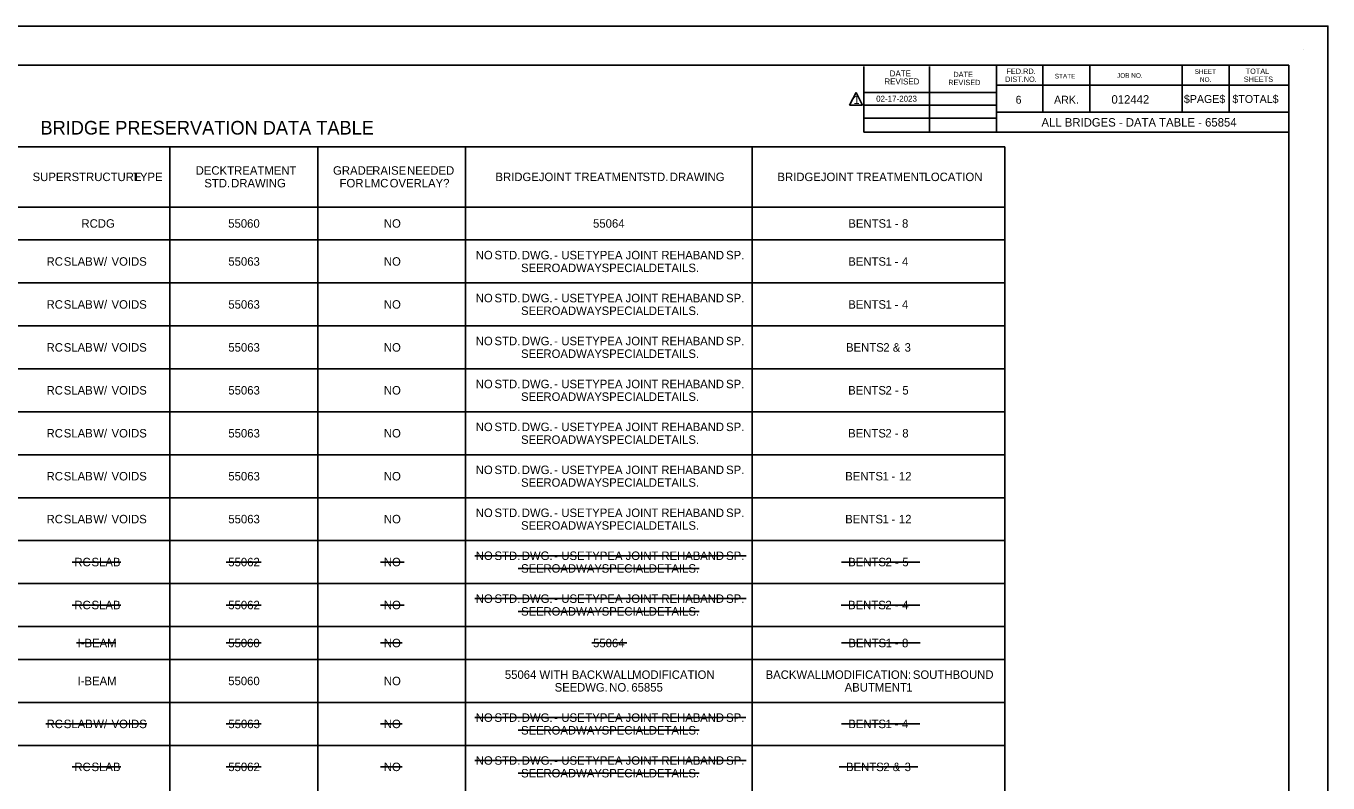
# Model space of a CAD drawing. Extents: x 18 to 14744716, y -5 to 1829144.
# Drawn here: x 32.59 to 51.78, y 5.47 to 16.63 of the extents above; entities that cross this region are included whole.
import ezdxf

# ---------------------------------------------------------------- set-up
doc = ezdxf.new("R2010")
doc.units = 0
for name, color, linetype in [('B_Copy In', 7, 'Continuous'), ('B_Dimensions', 7, 'Continuous'), ('B_Text', 7, 'Continuous'), ('B_Title Text', 7, 'Continuous'), ('R_Border', 7, 'Continuous'), ('R_No Plot', 7, 'Continuous')]:
    doc.layers.add(name, color=color, linetype=linetype)

msp = doc.modelspace()

# ---------------------------------------------------------------- linework, layer by layer
at = {"layer": 'B_Dimensions'}
for p, q in [((44.822, 15.648), (44.726, 15.464)), ((44.919, 15.464), (44.822, 15.648)), ((44.726, 15.464), (44.919, 15.464)), ((33.27, 8.729), (33.984, 8.729)), ((35.539, 8.729), (36.056, 8.729)), ((37.812, 8.729), (38.163, 8.729)), ((39.206, 8.823), (43.201, 8.823)), ((42.509, 8.636), (39.842, 8.636)), ((44.606, 8.729), (45.764, 8.729)), ((33.27, 8.096), (33.984, 8.096)), ((35.539, 8.096), (36.056, 8.096)), ((37.812, 8.096), (38.163, 8.096)), ((39.206, 8.19), (43.201, 8.19)), ((44.603, 8.096), (45.761, 8.096)), ((42.509, 8.003), (39.842, 8.003)), ((33.333, 7.537), (33.915, 7.537)), ((35.54, 7.537), (36.057, 7.537)), ((37.812, 7.537), (38.133, 7.537)), ((40.928, 7.537), (41.445, 7.537)), ((44.607, 7.537), (45.765, 7.537)), ((32.881, 6.344), (34.368, 6.344)), ((35.54, 6.344), (36.057, 6.344)), ((37.812, 6.344), (38.133, 6.344)), ((39.206, 6.438), (43.2, 6.438)), ((44.606, 6.345), (45.764, 6.345)), ((42.508, 6.251), (39.841, 6.251)), ((39.206, 5.805), (43.201, 5.805)), ((33.269, 5.712), (33.984, 5.712)), ((35.538, 5.712), (36.055, 5.712)), ((37.812, 5.712), (38.133, 5.712)), ((42.509, 5.618), (39.842, 5.618)), ((44.573, 5.712), (45.731, 5.712))]:
    msp.add_line(p, q, dxfattribs=at)
at = {"layer": 'B_Text'}
for p, q in [((23.2, 14.85), (47.013, 14.85)), ((34.711, -1.614), (34.711, 14.85)), ((36.889, -1.614), (36.889, 14.85)), ((39.067, -1.614), (39.067, 14.85)), ((43.29, -1.614), (43.29, 14.85)), ((47.013, -1.614), (47.013, 14.85)), ((23.2, 13.961), (47.013, 13.961)), ((24.356, 13.475), (47.013, 13.475)), ((24.356, 12.842), (47.013, 12.842)), ((24.356, 12.209), (47.013, 12.209)), ((24.356, 11.576), (47.013, 11.576)), ((24.356, 10.944), (47.013, 10.944)), ((24.356, 10.311), (47.013, 10.311)), ((24.356, 9.678), (47.013, 9.678)), ((24.356, 9.046), (47.013, 9.046)), ((24.356, 8.413), (47.013, 8.413)), ((23.2, 7.78), (47.013, 7.78)), ((24.356, 7.293), (47.013, 7.293)), ((24.356, 6.661), (47.013, 6.661)), ((24.356, 6.028), (47.013, 6.028))]:
    msp.add_line(p, q, dxfattribs=at)
at = {"layer": 'R_Border'}
for p, q in [((51.419, 16.281), (51.419, 16.281)), ((19.293, 16.051), (51.2, 16.051)), ((44.936, 15.063), (44.936, 16.031)), ((45.904, 15.063), (45.904, 16.031)), ((46.89, 16.051), (46.89, 15.063)), ((47.574, 16.051), (47.574, 15.357)), ((48.268, 16.051), (48.268, 15.357)), ((49.626, 16.051), (49.626, 15.357)), ((50.32, 16.051), (50.32, 15.357)), ((51.2, -4.796), (51.2, 16.051)), ((51.2, 15.757), (46.89, 15.757)), ((51.2, 15.759), (51.2, 15.759)), ((44.936, 15.649), (46.89, 15.649)), ((44.936, 15.463), (46.89, 15.463)), ((51.2, 15.357), (46.89, 15.357)), ((44.936, 15.269), (46.89, 15.269)), ((51.2, 15.063), (44.936, 15.063))]:
    msp.add_line(p, q, dxfattribs=at)
at = {"layer": 'R_No Plot'}
msp.add_lwpolyline([(17.777, 16.628), (51.777, 16.628), (51.777, -5.372), (17.777, -5.372)], close=True, dxfattribs=at)

# ---------------------------------------------------------------- texts
at = {"layer": 'B_Copy In'}
msp.add_text('ALL BRIDGES - DATA TABLE - 65854', height=0.1248, dxfattribs=at).set_placement((47.555, 15.146))
at = {"layer": 'B_Text'}
for s, height, p in [('1', 0.125, (44.782, 15.479)), ('012442', 0.1248, (48.586, 15.484)), ('SUPERSTRUCTURE', 0.1248, (32.686, 14.343)), (' TYPE', 0.1248, (34.12, 14.343)), ('DECK', 0.1248, (35.089, 14.437)), (' TREATMENT', 0.1248, (35.508, 14.437)), ('GRADE', 0.1248, (37.114, 14.437)), (' RAISE', 0.1248, (37.645, 14.437)), (' NEEDED', 0.1248, (38.158, 14.437)), ('BRIDGE', 0.1248, (39.507, 14.343)), (' JOINT', 0.1248, (40.1, 14.343)), (' TREATMENT', 0.1248, (40.626, 14.343)), (' STD.', 0.1248, (41.629, 14.343)), (' DRAWING', 0.1248, (42.031, 14.343)), ('BRIDGE', 0.1248, (43.663, 14.343)), (' JOINT', 0.1248, (44.257, 14.343)), (' TREATMENT', 0.1248, (44.782, 14.343)), (' LOCATION', 0.1248, (45.785, 14.343)), ('STD.', 0.1248, (35.217, 14.25)), (' DRAWING', 0.1248, (35.565, 14.25)), ('FOR', 0.1248, (37.21, 14.25)), (' LMC', 0.1248, (37.531, 14.25)), (' OVERLAY?', 0.1248, (37.902, 14.25)), ('RCDG', 0.1248, (33.406, 13.656)), ('55060', 0.1248, (35.569, 13.656)), ('NO', 0.1248, (37.863, 13.656)), ('55064', 0.1248, (40.946, 13.656)), ('BENTS', 0.1248, (44.708, 13.656)), (' 1', 0.1248, (45.212, 13.656)), (' -', 0.1248, (45.345, 13.656)), (' 8', 0.1248, (45.453, 13.656)), ('NO', 0.1248, (39.217, 13.19)), (' STD.', 0.1248, (39.447, 13.19)), (' DWG.', 0.1248, (39.849, 13.19)), (' -', 0.1248, (40.324, 13.19)), (' USE', 0.1248, (40.432, 13.19)), (' TYPE', 0.1248, (40.785, 13.19)), (' A', 0.1248, (41.223, 13.19)), (' JOINT', 0.1248, (41.38, 13.19)), (' REHAB', 0.1248, (41.906, 13.19)), (' AND', 0.1248, (42.478, 13.19)), (' SP.', 0.1248, (42.86, 13.19)), ('RC', 0.1248, (32.892, 13.096)), (' SLAB', 0.1248, (33.099, 13.096)), (' W/', 0.1248, (33.534, 13.096)), (' VOIDS', 0.1248, (33.803, 13.096)), ('55063', 0.1248, (35.571, 13.096)), ('NO', 0.1248, (37.863, 13.096)), ('SEE', 0.1248, (39.885, 13.002)), (' ROADWAY', 0.1248, (40.168, 13.002)), (' SPECIAL', 0.1248, (41.026, 13.002)), (' DETAILS.', 0.1248, (41.721, 13.002)), ('BENTS', 0.1248, (44.707, 13.096)), (' 1', 0.1248, (45.211, 13.096)), (' -', 0.1248, (45.344, 13.096)), (' 4', 0.1248, (45.452, 13.096)), ('NO', 0.1248, (39.217, 12.557)), (' STD.', 0.1248, (39.447, 12.557)), (' DWG.', 0.1248, (39.849, 12.557)), (' USE', 0.1248, (40.432, 12.557)), (' TYPE', 0.1248, (40.785, 12.557)), (' A', 0.1248, (41.223, 12.557)), (' JOINT', 0.1248, (41.38, 12.557)), (' REHAB', 0.1248, (41.906, 12.557)), (' AND', 0.1248, (42.478, 12.557)), (' SP.', 0.1248, (42.86, 12.557)), ('RC', 0.1248, (32.892, 12.463)), (' SLAB', 0.1248, (33.099, 12.463)), (' W/', 0.1248, (33.534, 12.463)), (' VOIDS', 0.1248, (33.803, 12.463)), ('55063', 0.1248, (35.571, 12.463)), ('NO', 0.1248, (37.863, 12.463)), ('SEE', 0.1248, (39.885, 12.37)), (' ROADWAY', 0.1248, (40.168, 12.37)), (' -', 0.1248, (40.324, 12.557)), (' SPECIAL', 0.1248, (41.026, 12.37)), (' DETAILS.', 0.1248, (41.721, 12.37)), ('BENTS', 0.1248, (44.707, 12.463)), (' 1', 0.1248, (45.211, 12.463)), (' -', 0.1248, (45.344, 12.463)), (' 4', 0.1248, (45.452, 12.463)), ('RC', 0.1248, (32.892, 11.83)), (' SLAB', 0.1248, (33.099, 11.83)), (' W/', 0.1248, (33.534, 11.83)), (' VOIDS', 0.1248, (33.803, 11.83)), ('55063', 0.1248, (35.571, 11.83)), ('NO', 0.1248, (37.863, 11.83)), ('NO', 0.1248, (39.217, 11.924)), (' STD.', 0.1248, (39.447, 11.924)), (' DWG.', 0.1248, (39.849, 11.924)), (' -', 0.1248, (40.324, 11.924)), (' USE', 0.1248, (40.432, 11.924)), (' TYPE', 0.1248, (40.785, 11.924)), (' A', 0.1248, (41.223, 11.924)), (' JOINT', 0.1248, (41.38, 11.924)), (' REHAB', 0.1248, (41.906, 11.924)), (' AND', 0.1248, (42.478, 11.924)), (' SP.', 0.1248, (42.86, 11.924)), ('BENTS', 0.1248, (44.674, 11.83)), (' 2', 0.1248, (45.177, 11.83)), (' &', 0.1248, (45.317, 11.83)), (' 3', 0.1248, (45.491, 11.83)), ('SEE', 0.1248, (39.885, 11.737)), (' ROADWAY', 0.1248, (40.168, 11.737)), (' SPECIAL', 0.1248, (41.026, 11.737)), (' DETAILS.', 0.1248, (41.721, 11.737)), ('RC', 0.1248, (32.892, 11.198)), (' SLAB', 0.1248, (33.099, 11.198)), (' W/', 0.1248, (33.534, 11.198)), (' VOIDS', 0.1248, (33.803, 11.198)), ('55063', 0.1248, (35.571, 11.198)), ('NO', 0.1248, (37.863, 11.198)), ('NO', 0.1248, (39.217, 11.291)), (' STD.', 0.1248, (39.447, 11.291)), (' DWG.', 0.1248, (39.849, 11.291)), (' -', 0.1248, (40.324, 11.291)), (' USE', 0.1248, (40.432, 11.291)), (' TYPE', 0.1248, (40.785, 11.291)), (' A', 0.1248, (41.223, 11.291)), (' JOINT', 0.1248, (41.38, 11.291)), (' REHAB', 0.1248, (41.906, 11.291)), (' AND', 0.1248, (42.478, 11.291)), (' SP.', 0.1248, (42.86, 11.291)), ('BENTS', 0.1248, (44.706, 11.198)), (' 2', 0.1248, (45.21, 11.198)), (' 5', 0.1248, (45.458, 11.198)), ('SEE', 0.1248, (39.885, 11.104)), (' ROADWAY', 0.1248, (40.168, 11.104)), (' SPECIAL', 0.1248, (41.026, 11.104)), (' DETAILS.', 0.1248, (41.721, 11.104)), (' -', 0.1248, (45.349, 11.198)), ('NO', 0.1248, (39.217, 10.659)), (' STD.', 0.1248, (39.447, 10.659)), (' DWG.', 0.1248, (39.849, 10.659)), (' USE', 0.1248, (40.432, 10.659)), (' TYPE', 0.1248, (40.785, 10.659)), (' A', 0.1248, (41.223, 10.659)), (' JOINT', 0.1248, (41.38, 10.659)), (' REHAB', 0.1248, (41.906, 10.659)), (' AND', 0.1248, (42.478, 10.659)), (' SP.', 0.1248, (42.86, 10.659)), ('RC', 0.1248, (32.892, 10.565)), (' SLAB', 0.1248, (33.099, 10.565)), (' W/', 0.1248, (33.534, 10.565)), (' VOIDS', 0.1248, (33.803, 10.565)), ('55063', 0.1248, (35.571, 10.565)), ('NO', 0.1248, (37.863, 10.565)), ('SEE', 0.1248, (39.885, 10.471)), (' ROADWAY', 0.1248, (40.168, 10.471)), (' -', 0.1248, (40.324, 10.659)), (' SPECIAL', 0.1248, (41.026, 10.471)), (' DETAILS.', 0.1248, (41.721, 10.471)), ('BENTS', 0.1248, (44.705, 10.565)), (' 2', 0.1248, (45.208, 10.565)), (' -', 0.1248, (45.348, 10.565)), (' 8', 0.1248, (45.457, 10.565)), ('RC', 0.1248, (32.892, 9.932)), (' SLAB', 0.1248, (33.099, 9.932)), (' W/', 0.1248, (33.534, 9.932)), (' VOIDS', 0.1248, (33.803, 9.932)), ('55063', 0.1248, (35.571, 9.932)), ('NO', 0.1248, (37.863, 9.932)), ('NO', 0.1248, (39.217, 10.026)), (' STD.', 0.1248, (39.447, 10.026)), (' DWG.', 0.1248, (39.849, 10.026)), (' -', 0.1248, (40.324, 10.026)), (' USE', 0.1248, (40.432, 10.026)), (' TYPE', 0.1248, (40.785, 10.026)), (' A', 0.1248, (41.223, 10.026)), (' JOINT', 0.1248, (41.38, 10.026)), (' REHAB', 0.1248, (41.906, 10.026)), (' AND', 0.1248, (42.478, 10.026)), (' SP.', 0.1248, (42.86, 10.026)), ('BENTS', 0.1248, (44.662, 9.932)), (' 1', 0.1248, (45.165, 9.932)), (' -', 0.1248, (45.299, 9.932)), (' 12', 0.1248, (45.407, 9.932)), ('SEE', 0.1248, (39.885, 9.839)), (' ROADWAY', 0.1248, (40.168, 9.839)), (' SPECIAL', 0.1248, (41.026, 9.839)), (' DETAILS.', 0.1248, (41.721, 9.839)), ('RC', 0.1248, (32.892, 9.3)), (' SLAB', 0.1248, (33.099, 9.3)), (' W/', 0.1248, (33.534, 9.3)), (' VOIDS', 0.1248, (33.803, 9.3)), ('55063', 0.1248, (35.571, 9.3)), ('NO', 0.1248, (37.863, 9.3)), ('NO', 0.1248, (39.217, 9.393)), (' STD.', 0.1248, (39.447, 9.393)), (' DWG.', 0.1248, (39.849, 9.393)), (' -', 0.1248, (40.324, 9.393)), (' USE', 0.1248, (40.432, 9.393)), (' TYPE', 0.1248, (40.785, 9.393)), (' A', 0.1248, (41.223, 9.393)), (' JOINT', 0.1248, (41.38, 9.393)), (' REHAB', 0.1248, (41.906, 9.393)), (' AND', 0.1248, (42.478, 9.393)), (' SP.', 0.1248, (42.86, 9.393)), ('BENTS', 0.1248, (44.662, 9.3)), (' 1', 0.1248, (45.165, 9.3)), (' 12', 0.1248, (45.407, 9.3)), ('SEE', 0.1248, (39.885, 9.206)), (' ROADWAY', 0.1248, (40.168, 9.206)), (' SPECIAL', 0.1248, (41.026, 9.206)), (' DETAILS.', 0.1248, (41.721, 9.206)), (' -', 0.1248, (45.299, 9.3)), ('NO', 0.1248, (39.217, 8.76)), (' STD.', 0.1248, (39.447, 8.76)), (' DWG.', 0.1248, (39.849, 8.76)), (' USE', 0.1248, (40.432, 8.76)), (' TYPE', 0.1248, (40.785, 8.76)), (' A', 0.1248, (41.223, 8.76)), (' JOINT', 0.1248, (41.38, 8.76)), (' REHAB', 0.1248, (41.906, 8.76)), (' AND', 0.1248, (42.478, 8.76)), (' SP.', 0.1248, (42.86, 8.76)), ('RC', 0.1248, (33.301, 8.667)), (' SLAB', 0.1248, (33.508, 8.667)), ('55062', 0.1248, (35.57, 8.667)), ('NO', 0.1248, (37.863, 8.667)), ('SEE', 0.1248, (39.885, 8.573)), (' ROADWAY', 0.1248, (40.168, 8.573)), (' -', 0.1248, (40.324, 8.76)), (' SPECIAL', 0.1248, (41.026, 8.573)), (' DETAILS.', 0.1248, (41.721, 8.573)), ('BENTS', 0.1248, (44.706, 8.667)), (' 2', 0.1248, (45.21, 8.667)), (' -', 0.1248, (45.349, 8.667)), (' 5', 0.1248, (45.458, 8.667)), ('NO', 0.1248, (39.217, 8.128)), (' STD.', 0.1248, (39.447, 8.128)), (' DWG.', 0.1248, (39.849, 8.128)), (' USE', 0.1248, (40.432, 8.128)), (' TYPE', 0.1248, (40.785, 8.128)), (' A', 0.1248, (41.223, 8.128)), (' JOINT', 0.1248, (41.38, 8.128)), (' REHAB', 0.1248, (41.906, 8.128)), (' AND', 0.1248, (42.478, 8.128)), (' SP.', 0.1248, (42.86, 8.128)), ('RC', 0.1248, (33.301, 8.034)), (' SLAB', 0.1248, (33.508, 8.034)), ('55062', 0.1248, (35.57, 8.034)), ('NO', 0.1248, (37.863, 8.034)), ('SEE', 0.1248, (39.885, 7.94)), (' ROADWAY', 0.1248, (40.168, 7.94)), (' -', 0.1248, (40.324, 8.128)), (' SPECIAL', 0.1248, (41.026, 7.94)), (' DETAILS.', 0.1248, (41.721, 7.94)), ('BENTS', 0.1248, (44.704, 8.034)), (' 2', 0.1248, (45.208, 8.034)), (' -', 0.1248, (45.347, 8.034)), (' 4', 0.1248, (45.456, 8.034)), ('I-BEAM', 0.1248, (33.349, 7.474)), ('55060', 0.1248, (35.569, 7.474)), ('NO', 0.1248, (37.863, 7.474)), ('55064', 0.1248, (40.946, 7.474)), ('BENTS', 0.1248, (44.708, 7.474)), (' 1', 0.1248, (45.212, 7.474)), (' -', 0.1248, (45.345, 7.474)), (' 8', 0.1248, (45.453, 7.474)), ('55064', 0.1248, (39.646, 7.008)), (' WITH', 0.1248, (40.11, 7.008)), (' BACKWALL', 0.1248, (40.586, 7.008)), (' MODIFICATION', 0.1248, (41.476, 7.008)), ('BACKWALL', 0.1248, (43.489, 7.008)), (' MODIFICATION:', 0.1248, (44.325, 7.008)), (' SOUTH', 0.1248, (45.613, 7.008)), (' BOUND', 0.1248, (46.199, 7.008)), ('I-BEAM', 0.1248, (33.349, 6.915)), ('55060', 0.1248, (35.569, 6.915)), ('NO', 0.1248, (37.863, 6.915)), ('SEE', 0.1248, (40.38, 6.821)), (' DWG.', 0.1248, (40.663, 6.821)), (' NO.', 0.1248, (41.138, 6.821)), (' 65855', 0.1248, (41.464, 6.821)), ('ABUTMENT', 0.1248, (44.654, 6.821)), (' 1', 0.1248, (45.515, 6.821)), ('RC', 0.1248, (32.892, 6.282)), (' SLAB', 0.1248, (33.099, 6.282)), (' W/', 0.1248, (33.534, 6.282)), (' VOIDS', 0.1248, (33.803, 6.282)), ('55063', 0.1248, (35.571, 6.282)), ('NO', 0.1248, (37.863, 6.282)), ('NO', 0.1248, (39.217, 6.375)), (' STD.', 0.1248, (39.447, 6.375)), (' DWG.', 0.1248, (39.849, 6.375)), (' -', 0.1248, (40.324, 6.375)), (' USE', 0.1248, (40.432, 6.375)), (' TYPE', 0.1248, (40.785, 6.375)), (' A', 0.1248, (41.223, 6.375)), (' JOINT', 0.1248, (41.38, 6.375)), (' REHAB', 0.1248, (41.906, 6.375)), (' AND', 0.1248, (42.478, 6.375)), (' SP.', 0.1248, (42.86, 6.375)), ('BENTS', 0.1248, (44.707, 6.282)), (' 1', 0.1248, (45.211, 6.282)), (' -', 0.1248, (45.344, 6.282)), (' 4', 0.1248, (45.452, 6.282)), ('SEE', 0.1248, (39.885, 6.188)), (' ROADWAY', 0.1248, (40.168, 6.188)), (' SPECIAL', 0.1248, (41.026, 6.188)), (' DETAILS.', 0.1248, (41.721, 6.188)), ('RC', 0.1248, (33.301, 5.649)), (' SLAB', 0.1248, (33.508, 5.649)), ('55062', 0.1248, (35.57, 5.649)), ('NO', 0.1248, (37.863, 5.649)), ('NO', 0.1248, (39.217, 5.743)), (' STD.', 0.1248, (39.447, 5.743)), (' DWG.', 0.1248, (39.849, 5.743)), (' -', 0.1248, (40.324, 5.743)), (' USE', 0.1248, (40.432, 5.743)), (' TYPE', 0.1248, (40.785, 5.743)), (' A', 0.1248, (41.223, 5.743)), (' JOINT', 0.1248, (41.38, 5.743)), (' REHAB', 0.1248, (41.906, 5.743)), (' AND', 0.1248, (42.478, 5.743)), (' SP.', 0.1248, (42.86, 5.743)), ('BENTS', 0.1248, (44.674, 5.649)), (' 2', 0.1248, (45.177, 5.649)), (' &', 0.1248, (45.317, 5.649)), (' 3', 0.1248, (45.491, 5.649)), ('SEE', 0.1248, (39.885, 5.556)), (' ROADWAY', 0.1248, (40.168, 5.556)), (' SPECIAL', 0.1248, (41.026, 5.556)), (' DETAILS.', 0.1248, (41.721, 5.556))]:
    msp.add_text(s, height=height, dxfattribs=at).set_placement(p)
at = {"layer": 'B_Title Text'}
msp.add_text('BRIDGE PRESERVATION DATA TABLE', height=0.2004, dxfattribs=at).set_placement((32.802, 15.029))
at = {"layer": 'R_Border'}
for s, height, p in [('DATE', 0.0879, (45.318, 15.885)), ('DATE', 0.0782, (46.256, 15.875)), ('FED.RD.', 0.0782, (47.038, 15.923)), ('JOB NO.', 0.0684, (48.668, 15.865)), ('SHEET', 0.0684, (49.812, 15.923)), ('TOTAL', 0.0782, (50.564, 15.923)), ('REVISED', 0.0879, (45.24, 15.767)), ('REVISED', 0.0782, (46.181, 15.757)), ('DIST.NO.', 0.0782, (47.018, 15.805)), ('STATE', 0.0684, (47.75, 15.855)), ('NO.', 0.0684, (49.89, 15.805)), ('SHEETS', 0.0782, (50.536, 15.805)), ('02-17-2023', 0.0879, (45.118, 15.513)), ('6', 0.117, (47.174, 15.483)), ('ARK.', 0.1172, (47.74, 15.483)), ('$PAGE$', 0.1172, (49.654, 15.494)), ('$TOTAL$', 0.1172, (50.369, 15.494))]:
    msp.add_text(s, height=height, dxfattribs=at).set_placement(p)

doc.saveas('drawing.dxf')
